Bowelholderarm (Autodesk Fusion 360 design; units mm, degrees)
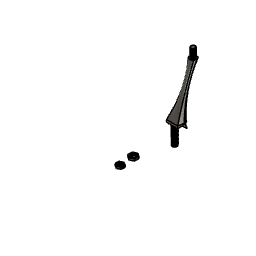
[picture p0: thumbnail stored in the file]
sketch "Sketch1" plane through (0, 0, 0) normal (0, 0, 1) x axis (1, 0, 0)
  line L1 (23.5, 0) -> (0, 0)
  line L2 (23.5, 11.5) -> (23.5, 0)
  line L3 (0, 11.5) -> (23.5, 11.5)
  line L4 (0, 0) -> (0, 11.5)
  point P1 (0, 0)
  point P2 (0, 0)
  point P3 (23.5, 0)
  point P5 (0, 11.5)
  horizontal L1
  vertical L2
  horizontal L3
  vertical L4
  coincident P1 P2
  dimension "d1" distance P2 P3 = 23.5
  dimension "d2" distance P2 P5 = 11.5
work_plane "WorkPlane1" AlongDistance 40
sketch "Sketch2" plane through (0, 0, 40) normal (0, 0, 1) x axis (1, 0, 0)
  line L1 (0, 11.5) -> (23.5, 11.5)
  line L2 (23.5, 11.5) -> (23.5, 0)
  line L3 (23.5, 0) -> (0, 0)
  line L4 (0, 0) -> (0, 11.5)
work_plane "WorkPlane2" sketch "Sketch2" AlongDistance 100
sketch "Sketch3" plane through (11.75, 5.75, 140) normal (0, 0, 1) x axis (1, 0, 0)
  line L1 (11.5, 65) -> (-12, 65)
  line L2 (11.5, 53.5) -> (11.5, 65)
  line L3 (-12, 53.5) -> (11.5, 53.5)
  line L4 (-12, 65) -> (-12, 53.5)
  circle C1 centre (-0.25, 58.986) radius 5.1941
  point P2 (-12, 65)
  point P3 (11.5, 65)
  point P5 (-12, 53.5)
  horizontal L1
  vertical L2
  horizontal L3
  vertical L4
  dimension "d5" distance P2 P3 = 23.5
  dimension "d6" distance P2 P5 = 11.5
work_plane "WorkPlane3" AlongDistance 60
sketch "Sketch4" plane through (0, 0, 60) normal (0, 0, 1) x axis (1, 0, 0)
  line L1 (23.5, 35.6028) -> (0, 35.6028)
  line L2 (23.5, 24.1028) -> (23.5, 35.6028)
  line L3 (0, 24.1028) -> (23.5, 24.1028)
  line L4 (0, 35.6028) -> (0, 24.1028)
  circle C1 centre (11.75, 29.8528) radius 5.0405
  point P2 (0, 35.6028)
  point P3 (23.5, 35.6028)
  point P5 (0, 24.1028)
  horizontal L1
  vertical L2
  horizontal L3
  vertical L4
  dimension "d8" distance P2 P3 = 23.5
  dimension "d9" distance P2 P5 = 11.5
loft "Loft1"
sketch "Sketch5" plane through (0, 0, 0) normal (1, 0, 0) x axis (0, 1, 0)
  line L1 (17, 35) -> (-10, 35)
  line L2 (17, 30) -> (17, 35)
  line L3 (-10, 30) -> (17, 30)
  line L4 (-10, 35) -> (-10, 30)
  horizontal L1
  vertical L2
  horizontal L3
  vertical L4
extrude "Extrude1" add sketch "Sketch5" along normal blind 32.5 and against normal blind 10
fillet "Fillet1" radius 5 1
sketch "Sketch6" plane through (0, 0, 0) normal (0, 1, 0) x axis (1, 0, 0)
  line L1 (-5, 0) -> (0, 0)
  line L2 (-5, -30) -> (-5, 0)
  line L3 (0, -30) -> (-5, -30)
  line L4 (0, 0) -> (0, -30)
  point P1 (0, 0)
  point P2 (0, 0)
  horizontal L1
  vertical L2
  horizontal L3
  vertical L4
  coincident P1 P2
extrude "Extrude2" cut sketch "Sketch6" along normal blind 23 and against normal blind 14
sketch "Sketch7" plane through (0, 0, 0) normal (0, 1, 0) x axis (1, 0, 0)
  line L1 (28, 0.0234) -> (23.5118, 0.0234)
  line L2 (28, -30) -> (28, 0.0234)
  line L3 (23.5118, -30) -> (28, -30)
  line L4 (23.5118, 0.0234) -> (23.5118, -30)
  horizontal L1
  vertical L2
  horizontal L3
  vertical L4
extrude "Extrude3" cut sketch "Sketch7" along normal blind 19 and against normal blind 20
sketch "Sketch8" plane through (23.5118, 0, 0) normal (1, 0, 0) x axis (0, 1, 0)
  curve K1 (11.4664, 0.1133) -> (8.4976, 30)
  line L1 (-3.9716, 30) -> (8.4976, 30)
  curve K2 (-3.9716, 30) -> (-0.0452, 0.1133)
  curve K3 (-0.0452, 0.1133) -> (11.4664, 0.1133)
  line L2 (-9, 0) -> (-4, 0)
  line L3 (-9, 30) -> (-9, 0)
  line L4 (-4, 30) -> (-9, 30)
  line L5 (-4, 0) -> (-4, 30)
  horizontal L2
  vertical L3
  horizontal L4
  vertical L5
extrude "Extrude4" cut sketch "Sketch8" profile of K2 L2 L3 L4 L5 against normal blind 36
hole "Hole1" HoleDepth 26 HoleDiameter 5.035 TipAngle 180
sketch "Sketch9" plane through (0, 0, 30) normal (0, 0, -1) x axis (1, 0, 0)
  line L1 (-10, -17) -> (-10, 10)
  line L2 (32.5, -17) -> (-10, -17)
  line L3 (32.5, 10) -> (32.5, -17)
  line L4 (-10, 10) -> (32.5, 10)
  curve K1 (23.5118, -8.4976) -> (0, -8.4972)
  line L5 (0, 3.9712) -> (0, -8.4972)
  curve K2 (0, 3.9712) -> (23.5118, 3.9716)
  line L6 (23.5118, -8.4976) -> (23.5118, 3.9716)
sketch "Sketch10" plane through (0, 0, 141.7507) normal (0, 0, 1) x axis (-1, 0, 0)
  line L1 (-84.7048, 102.1717) -> (-91.0185, 102.1717)
  line L2 (-84.7048, 77.1717) -> (-84.7048, 102.1717)
  line L3 (-90.8302, 77.1717) -> (-84.7048, 77.1717)
  line L4 (-25.7275, 19.3556) -> (-25.7275, 13.0419)
  line L5 (-0.7275, 19.3556) -> (-25.7275, 19.3556)
  line L6 (-0.7275, 13.2301) -> (-0.7275, 19.3556)
  line L7 (57.0886, 78.3328) -> (63.4023, 78.3328)
  line L8 (57.0886, 103.3328) -> (57.0886, 78.3328)
  line L9 (63.2141, 103.3328) -> (57.0886, 103.3328)
  line L10 (-1.8887, 161.1489) -> (-1.8887, 167.4627)
  line L11 (-26.8887, 161.1489) -> (-1.8887, 161.1489)
  line L12 (-26.8887, 167.2744) -> (-26.8887, 161.1489)
  line L13 (-25.5, 7) -> (-1, 7)
  line L14 (-25.5, 19) -> (-25.5, 7)
  line L15 (-1, 19) -> (-25.5, 19)
  line L16 (-1, 7) -> (-1, 19)
  arc A1 centre (-13.8081, 90.2523) radius 78.125 clockwise from (-25.7275, 13.0419) to (-90.8302, 77.1717)
  arc A2 centre (-13.8081, 90.2523) radius 78.125 clockwise from (63.4023, 78.3328) to (-0.7275, 13.2301)
  arc A3 centre (-13.8081, 90.2523) radius 78.125 clockwise from (-1.8887, 167.4627) to (63.2141, 103.3328)
  arc A4 centre (-13.8081, 90.2523) radius 78.125 clockwise from (-91.0185, 102.1717) to (-26.8887, 167.2744)
  horizontal L13
  vertical L14
  horizontal L15
  vertical L16
extrude "Extrude5" new body sketch "Sketch10" profile of L13 L14 L15 L16 along normal blind 5
sketch "Sketch11" plane through (0, 0, 146.7507) normal (0, 0, 1) x axis (-1, 0, 0)
  line L1 (-25.5, 19) -> (-1, 19)
  line L2 (-25.5, 7) -> (-25.5, 19)
  line L3 (-1, 7) -> (-25.5, 7)
  line L4 (-1, 19) -> (-1, 7)
  line L5 (-25.7068, 19.3487) -> (-0.2932, 19.3487)
  parallel L1 L5
work_plane "WorkPlane4" sketch "Sketch11" AlongDistance 30
work_plane "WorkPlane5" sketch "Sketch11" AlongDistance 100
sketch "Sketch12" plane through (13.25, -13, 176.7507) normal (0, 0, 1) x axis (1, 0, 0)
  circle C1 centre (0, 15) radius 7.5
  dimension "d35" diameter C1 = 15
sketch "Sketch14" plane through (0, 0, 0) normal (0, 0, 1) x axis (1, 0, 0)
sketch "Sketch15" plane through (13.25, -13, 246.7507) normal (0, 0, 1) x axis (1, 0, 0)
  circle C1 centre (0, 40) radius 7.5
  dimension "d37" diameter C1 = 15
sketch "Sketch16" plane through (25.5, 0, 0) normal (1, 0, 0) x axis (0, 1, 0)
  line L1 (-7, 141.7507) -> (-19, 141.7507)
  line L2 (-7, 146.7507) -> (-7, 141.7507)
  line L3 (-19, 141.7507) -> (-19, 146.7507)
  line L4 (-19, 146.7507) -> (-7, 146.7507)
sketch "Sketch17" plane through (25.5, 0, 0) normal (1, 0, 0) x axis (0, 1, 0)
  line L1 (2.4924, 130.2525) -> (1.1257, 146.6522)
  line L2 (-7, 146.7676) -> (-7, 145)
  line L3 (1.1257, 146.7676) -> (-7, 146.7676)
  line L4 (1.1257, 146.6522) -> (1.1257, 146.7676)
  arc A1 centre (-42.6408, 111.6307) radius 48.8239 clockwise from (-7, 145) to (2.4924, 130.2525)
  vertical L2
  perpendicular L2 L3
extrude "Extrude6" add sketch "Sketch17" along normal blind 2 and against normal blind 27
fillet "Fillet2" radius 5
sketch "Sketch18" plane through (0, 0, 146.7507) normal (0, 0, 1) x axis (-1, 0, 0)
  line L1 (1.5132, 6.9277) -> (-1, 19)
  line L2 (1.5132, 3.2652) -> (1.5132, 6.9277)
  line L3 (-25.5, 19) -> (-1, 19)
  line L4 (-27.5, 7) -> (-25.5, 19)
  line L5 (-27.5, 3.5) -> (-27.5, 7)
  line L6 (-23.6, -1.1) -> (-2.4, -1.1)
  arc A1 centre (-22.2302, 4.0146) radius 5.2949 clockwise from (-23.6, -1.1) to (-27.5, 3.5)
  arc A2 centre (-4.0636, 4.328) radius 5.6772 clockwise from (1.5132, 3.2652) to (-2.4, -1.1)
  vertical L2
  horizontal L3
  perpendicular L3 L5
  horizontal L6
loft "Loft5" sketch "Sketch18" + "Sketch12" + "Sketch15"
sketch "Sketch19" plane through (13.25, -13, 246.7507) normal (0, 0, 1) x axis (1, 0, 0)
sketch "Sketch20" plane through (0, 0, 0) normal (0, 1, 0) x axis (1, 0, 0)
sketch "Sketch21" plane through (0, 0, 141.7507) normal (0, 0, 1) x axis (-1, 0, 0)
  circle C1 centre (-13.5, 13.5) radius 5.3151
extrude "Extrude8" add sketch "Sketch21" against normal blind 40
thread "Thread2"
sketch "Sketch22" plane through (13.25, -13, 246.7507) normal (0, 0, 1) x axis (1, 0, 0)
  circle C1 centre (0, 40) radius 5
  dimension "d48" diameter C1 = 10
extrude "Extrude9" add sketch "Sketch22" along normal blind 20
thread "Thread3"
sketch "Sketch23" plane through (0, 0, 0) normal (0, 0, 1) x axis (1, 0, 0)
  line L1 (-110.3462, 10.7689) -> (-118.1675, 15.6843)
  line L2 (-102.1787, 15.0846) -> (-110.3462, 10.7689)
  line L3 (-101.8325, 24.3157) -> (-102.1787, 15.0846)
  line L4 (-109.6538, 29.2311) -> (-101.8325, 24.3157)
  line L5 (-117.8213, 24.9154) -> (-109.6538, 29.2311)
  line L6 (-118.1675, 15.6843) -> (-117.8213, 24.9154)
  point P8 (-110, 20)
  dimension "d51" distance P8 L6 = 8
extrude "Extrude10" new body sketch "Sketch23" along normal blind 4
sketch "Sketch24" plane through (0, 0, 4) normal (0, 0, 1) x axis (-1, 0, 0)
  line L1 (118.1675, -15.6843) -> (117.8213, -24.9154)
  line L2 (110.3462, -10.7689) -> (118.1675, -15.6843)
  line L3 (102.1787, -15.0846) -> (110.3462, -10.7689)
  line L4 (101.8325, -24.3157) -> (102.1787, -15.0846)
  line L5 (109.6538, -29.2311) -> (101.8325, -24.3157)
  line L6 (117.8213, -24.9154) -> (109.6538, -29.2311)
  circle C1 centre (110, -20) radius 5
  dimension "d54" diameter C1 = 10
extrude "Extrude11" cut sketch "Sketch24" profile of C1 against normal blind 5
thread "Thread4"
copy_paste_bodies "CopyPasteBodies1"
move "Move1"
scale "Scale1" ScaleFactor 0.9
move "Move2"
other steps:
thread "Thread1"
base_feature "Base Feature"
